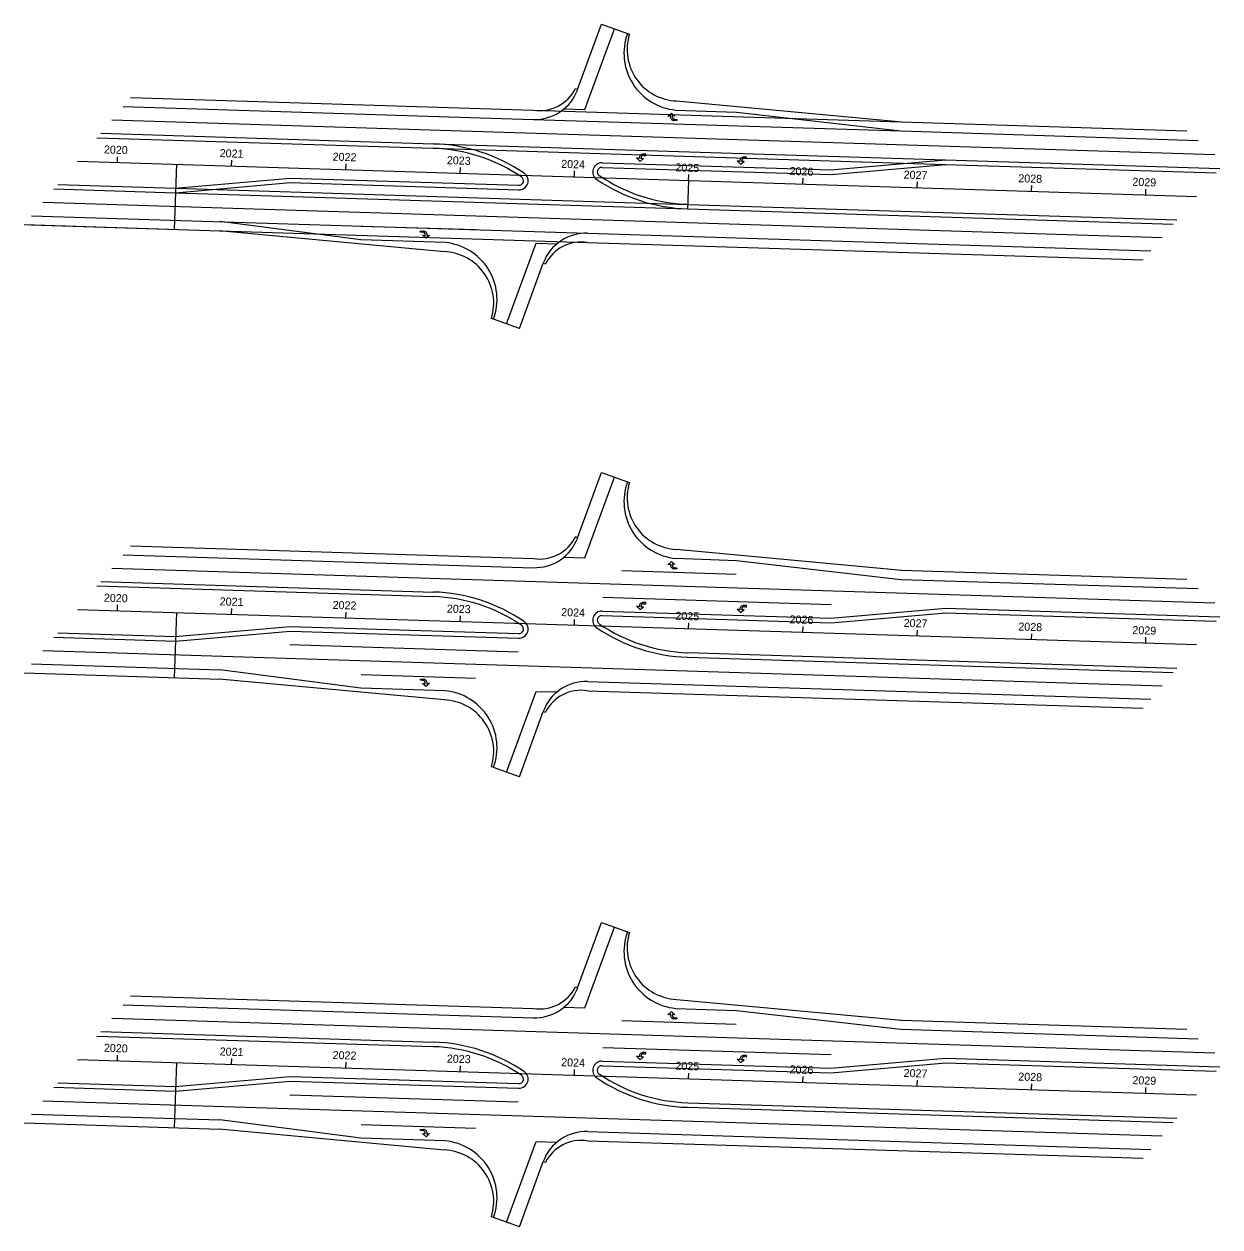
# Model space of a CAD drawing. Extents: x 8527 to 36635, y 12099 to 39012.
# Drawn here: x 11842 to 12888, y 32018 to 33071 of the extents above; entities that cross this region are included whole.
import ezdxf

# ---------------------------------------------------------------- set-up
doc = ezdxf.new("R2010")
doc.units = 0
for name, color, linetype in [('DR_P_Inlet_Protection', 7, 'Continuous'), ('DT_P_Tie', 7, 'Continuous'), ('MT_P_Dotted_Line', 7, 'Continuous'), ('MT_P_Text', 7, 'Continuous'), ('MT_P_Traffic_Attenuator', 7, 'Continuous'), ('PV_X_EOP', 7, 'Continuous'), ('RD_P_Concrete_Barrier', 7, 'Continuous'), ('SH_Text', 7, 'Continuous')]:
    doc.layers.add(name, color=color, linetype=linetype)

msp = doc.modelspace()

# ---------------------------------------------------------------- linework, layer by layer
at = {"layer": 'DR_P_Inlet_Protection'}
for p, q in [((11918.7, 32986.7), (12883.6, 32956.3)), ((11858.2, 32914.6), (12837.3, 32883.7)), ((11918.7, 32594.6), (12883.6, 32564.2)), ((11858.2, 32522.5), (12837.3, 32491.6)), ((11918.7, 32200.9), (12883.6, 32170.5)), ((11858.2, 32128.8), (12837.3, 32097.9))]:
    msp.add_line(p, q, dxfattribs=at)
at = {"layer": 'DT_P_Tie'}
for p, q in [((12314.1, 32996.3), (12332.4, 32995.7)), ((12289.7, 32879), (12308.1, 32878.4)), ((12314.1, 32604.1), (12332.4, 32603.6)), ((12289.7, 32486.8), (12308.1, 32486.3)), ((12314.1, 32210.5), (12332.4, 32209.9)), ((12289.7, 32093.2), (12308.1, 32092.6))]:
    msp.add_line(p, q, dxfattribs=at)
at = {"layer": 'MT_P_Dotted_Line'}
for p, q in [((12332.4, 32995.7), (12358.3, 33066.4)), ((12263.8, 32808.3), (12289.7, 32879)), ((12332.4, 32603.6), (12358.3, 32674.3)), ((12263.8, 32416.1), (12289.7, 32486.8)), ((12332.4, 32209.9), (12358.3, 32280.6)), ((12263.8, 32022.5), (12289.7, 32093.2))]:
    msp.add_line(p, q, dxfattribs=at)
at = {"layer": 'MT_P_Text'}
for p, q in [((11923.5, 32949.6), (11923.6, 32954.5)), ((11888.5, 32950.7), (12867.5, 32919.8)), ((12023.4, 32946.4), (12023.6, 32951.4)), ((12123.4, 32943.3), (12123.6, 32948.3)), ((12223.3, 32940.1), (12223.5, 32945.1)), ((12323.3, 32937), (12323.5, 32942)), ((12423.2, 32933.8), (12423.4, 32938.8)), ((12523.2, 32930.7), (12523.4, 32935.7)), ((12623.1, 32927.5), (12623.3, 32932.5)), ((12723.1, 32924.4), (12723.3, 32929.4)), ((12823, 32921.2), (12823.2, 32926.2)), ((11888.5, 32558.5), (12867.5, 32527.7)), ((11923.5, 32557.4), (11923.6, 32562.4)), ((12023.4, 32554.3), (12023.6, 32559.3)), ((12123.4, 32551.1), (12123.6, 32556.1)), ((12223.3, 32548), (12223.5, 32553)), ((12323.3, 32544.8), (12323.5, 32549.8)), ((12423.2, 32541.7), (12423.4, 32546.7)), ((12523.2, 32538.5), (12523.4, 32543.5)), ((12623.1, 32535.4), (12623.3, 32540.4)), ((12723.1, 32532.2), (12723.3, 32537.2)), ((12823, 32529.1), (12823.2, 32534.1)), ((11923.5, 32163.7), (11923.6, 32168.7)), ((12023.4, 32160.6), (12023.6, 32165.6)), ((11888.5, 32164.8), (12867.5, 32134)), ((12123.4, 32157.4), (12123.6, 32162.4)), ((12223.3, 32154.3), (12223.5, 32159.3)), ((12323.3, 32151.1), (12323.5, 32156.1)), ((12423.2, 32148), (12423.4, 32153)), ((12523.2, 32144.9), (12523.4, 32149.8)), ((12623.1, 32141.7), (12623.3, 32146.7)), ((12723.1, 32138.6), (12723.3, 32143.6)), ((12823, 32135.4), (12823.2, 32140.4))]:
    msp.add_line(p, q, dxfattribs=at)
at = {"layer": 'MT_P_Traffic_Attenuator'}
for p, q in [((12369.6, 33062.3), (12371.5, 33061.6)), ((12326.1, 33013.3), (12324.3, 33014)), ((11935.1, 33006.2), (12287.6, 32995.1)), ((12412.7, 33003.3), (12609.7, 32985)), ((12609.2, 32985), (12858.9, 32977.1)), ((11905.6, 32971.1), (12199.7, 32961.9)), ((12347.5, 32945.2), (12547.4, 32938.9)), ((12547.8, 32938.9), (12648.2, 32947.8)), ((12647.7, 32947.7), (12884.7, 32940.3)), ((11974, 32926.9), (12074.5, 32935.8)), ((12074.5, 32935.8), (12274.7, 32929.5)), ((11871.3, 32930.2), (11974.4, 32926.9)), ((12422.4, 32912.8), (12850.3, 32899.3)), ((11841.8, 32895.1), (12013, 32889.7)), ((12209.5, 32871.4), (12012.5, 32889.7)), ((12334.6, 32879.6), (12820.9, 32864.3)), ((12296, 32861.3), (12297.9, 32860.7)), ((12252.5, 32812.4), (12250.6, 32813.1)), ((12369.6, 32670.1), (12371.5, 32669.4)), ((12326.1, 32621.2), (12324.3, 32621.9)), ((11935.1, 32614.1), (12287.6, 32603)), ((12412.7, 32611.1), (12609.7, 32592.8)), ((12609.2, 32592.8), (12858.9, 32585)), ((11905.6, 32579), (12199.7, 32569.7)), ((12547.8, 32546.8), (12648.2, 32555.6)), ((12647.7, 32555.6), (12884.7, 32548.1)), ((12347.5, 32553.1), (12547.4, 32546.8)), ((11871.3, 32538), (11974.4, 32534.8)), ((11974, 32534.8), (12074.5, 32543.7)), ((12074.5, 32543.7), (12274.7, 32537.3)), ((12422.4, 32520.7), (12850.3, 32507.2)), ((11841.8, 32503), (12013, 32497.6)), ((12209.5, 32479.3), (12012.5, 32497.6)), ((12334.6, 32487.4), (12820.9, 32472.1)), ((12296, 32469.2), (12297.9, 32468.5)), ((12252.5, 32420.3), (12250.6, 32421)), ((12369.6, 32276.5), (12371.5, 32275.8)), ((11935.1, 32220.4), (12287.6, 32209.3)), ((12326.1, 32227.5), (12324.3, 32228.2)), ((12412.7, 32217.4), (12609.7, 32199.1)), ((12609.2, 32199.2), (12858.9, 32191.3)), ((11905.6, 32185.3), (12199.7, 32176.1)), ((12347.5, 32159.4), (12547.4, 32153.1)), ((12547.8, 32153.1), (12648.2, 32162)), ((12647.7, 32161.9), (12884.7, 32154.5)), ((11871.3, 32144.4), (11974.4, 32141.1)), ((11974, 32141.1), (12074.5, 32150)), ((12074.5, 32150), (12274.7, 32143.7)), ((12422.4, 32127), (12850.3, 32113.5)), ((11841.8, 32109.3), (12013, 32103.9)), ((12209.5, 32085.6), (12012.5, 32103.9)), ((12334.6, 32093.8), (12820.9, 32078.4)), ((12296, 32075.5), (12297.9, 32074.9)), ((12252.5, 32026.6), (12250.6, 32027.3))]:
    msp.add_line(p, q, dxfattribs=at)
for centre, radius, start, end in [((12414.5, 33048.3), 45.1, 162.8175, 267.6295), ((12292.8, 33030), 35.2, 261.4285, 333.1119), ((12195.1, 32815.9), 146, 55.8753, 88.1958), ((12347.3, 32941.2), 4, 88.1958, 235.8753), ((12274.8, 32933.5), 4, 268.1958, 55.8753), ((12427, 33058.8), 146, 235.8753, 268.1958), ((12207.6, 32826.4), 45.1, 342.8175, 87.6295), ((12329.3, 32844.7), 35.2, 81.4285, 153.1119), ((12414.5, 32656.1), 45.1, 162.8175, 267.6295), ((12292.8, 32637.8), 35.2, 261.4285, 333.1119), ((12195.1, 32423.8), 146, 55.8753, 88.1958), ((12274.8, 32541.3), 4, 268.1958, 55.8753), ((12347.3, 32549.1), 4, 88.1958, 235.8753), ((12427, 32666.6), 146, 235.8753, 268.1958), ((12329.3, 32452.6), 35.2, 81.4285, 153.1119), ((12207.6, 32434.3), 45.1, 342.8175, 87.6295), ((12414.5, 32262.5), 45.1, 162.8175, 267.6295), ((12292.8, 32244.2), 35.2, 261.4285, 333.1119), ((12195.1, 32030.1), 146, 55.8753, 88.1958), ((12347.3, 32155.4), 4, 88.1958, 235.8753), ((12274.8, 32147.7), 4, 268.1958, 55.8753), ((12427, 32272.9), 146, 235.8753, 268.1958), ((12329.3, 32058.9), 35.2, 81.4285, 153.1119), ((12207.6, 32040.6), 45.1, 342.8175, 87.6295)]:
    msp.add_arc(centre, radius, start, end, dxfattribs=at)
at = {"layer": 'PV_X_EOP'}
for p, q in [((12287.3, 32987.1), (12608.9, 32977)), ((12287.6, 32995.1), (12609.2, 32985)), ((12199.9, 32965.9), (12647.8, 32951.7)), ((12199.7, 32961.9), (12647.7, 32947.7)), ((11974.3, 32922.9), (12422.3, 32908.8)), ((11974.4, 32926.9), (12422.4, 32912.8)), ((12136.8, 32893.8), (12236.8, 32890.7)), ((12364.8, 32592.5), (12464.8, 32589.4)), ((12348, 32569.1), (12547.9, 32562.8)), ((12074.3, 32527.7), (12274.2, 32521.4)), ((12136.8, 32501.7), (12236.8, 32498.5)), ((12364.8, 32198.9), (12464.8, 32195.7)), ((12348, 32175.4), (12547.9, 32169.1)), ((12074.3, 32134), (12274.2, 32127.7)), ((12136.8, 32108), (12236.8, 32104.8))]:
    msp.add_line(p, q, dxfattribs=at)
at = {"layer": 'RD_P_Concrete_Barrier'}
for p, q in [((12405, 32989.7), (12408.2, 32992.6)), ((12407.3, 32990.3), (12405, 32989.7)), ((12405, 32989.7), (12405, 32989.7)), ((12407.2, 32989.7), (12407.3, 32990.3)), ((12408.2, 32992.6), (12411.1, 32989.9)), ((12408.9, 32990.3), (12408.8, 32989.6)), ((12411.1, 32989.9), (12408.9, 32990.3)), ((12412.9, 32986.1), (12410.4, 32986.2)), ((12411.1, 32987.2), (12412.9, 32987.1)), ((12412.9, 32987.1), (12412.9, 32986.1)), ((12413, 32989.5), (12413, 32989.5)), ((12385.9, 32956.6), (12383.4, 32956.7)), ((12384, 32955.7), (12385.8, 32955.6)), ((12385.8, 32955.6), (12385.9, 32956.6)), ((12377.7, 32953.5), (12377.7, 32953.5)), ((12380, 32952.8), (12377.7, 32953.5)), ((12377.7, 32953.5), (12380.7, 32950.4)), ((12380, 32953.5), (12380, 32952.8)), ((12380.7, 32950.4), (12383.8, 32953)), ((12381.6, 32952.7), (12381.6, 32953.4)), ((12383.8, 32953), (12381.6, 32952.7)), ((12385.7, 32953.3), (12385.7, 32953.3)), ((12465.7, 32951), (12465.7, 32951)), ((12468, 32950.2), (12465.7, 32951)), ((12465.7, 32951), (12468.7, 32947.9)), ((12468, 32950.9), (12468, 32950.2)), ((12468.7, 32947.9), (12471.8, 32950.4)), ((12469.6, 32950.2), (12469.6, 32950.9)), ((12471.8, 32950.4), (12469.6, 32950.2)), ((12473.8, 32954), (12471.4, 32954.1)), ((12472, 32953.1), (12473.8, 32953)), ((12473.7, 32950.7), (12473.7, 32950.7)), ((12473.8, 32953), (12473.8, 32954)), ((12188.6, 32886.3), (12188.6, 32886.3)), ((12188.7, 32888.6), (12188.7, 32889.6)), ((12188.7, 32889.6), (12191.2, 32889.5)), ((12190.6, 32888.5), (12188.7, 32888.6)), ((12193.5, 32883.1), (12190.5, 32885.9)), ((12190.5, 32885.9), (12192.7, 32885.5)), ((12192.7, 32885.5), (12192.8, 32886.2)), ((12196.6, 32886), (12193.5, 32883.1)), ((12194.4, 32886.1), (12194.3, 32885.4)), ((12194.3, 32885.4), (12196.6, 32886)), ((12196.6, 32886), (12196.6, 32886)), ((12405, 32597.6), (12408.2, 32600.5)), ((12407.3, 32598.2), (12405, 32597.6)), ((12405, 32597.6), (12405, 32597.6)), ((12407.2, 32597.5), (12407.3, 32598.2)), ((12408.2, 32600.5), (12411.1, 32597.7)), ((12408.9, 32598.1), (12408.8, 32597.4)), ((12411.1, 32597.7), (12408.9, 32598.1)), ((12413, 32597.3), (12413, 32597.3)), ((12412.9, 32594), (12410.4, 32594.1)), ((12411.1, 32595.1), (12412.9, 32595)), ((12412.9, 32595), (12412.9, 32594)), ((12377.7, 32561.4), (12377.7, 32561.4)), ((12380, 32560.7), (12377.7, 32561.4)), ((12377.7, 32561.4), (12380.7, 32558.3)), ((12380, 32561.3), (12380, 32560.7)), ((12380.7, 32558.3), (12383.8, 32560.9)), ((12381.6, 32560.6), (12381.6, 32561.3)), ((12383.8, 32560.9), (12381.6, 32560.6)), ((12385.9, 32564.5), (12383.4, 32564.5)), ((12384, 32563.5), (12385.8, 32563.5)), ((12385.7, 32561.1), (12385.7, 32561.1)), ((12385.8, 32563.5), (12385.9, 32564.5)), ((12465.7, 32558.8), (12465.7, 32558.8)), ((12468, 32558.1), (12465.7, 32558.8)), ((12465.7, 32558.8), (12468.7, 32555.7)), ((12468, 32558.7), (12468, 32558.1)), ((12468.7, 32555.7), (12471.8, 32558.3)), ((12469.6, 32558), (12469.6, 32558.7)), ((12471.8, 32558.3), (12469.6, 32558)), ((12473.8, 32561.9), (12471.4, 32562)), ((12472, 32560.9), (12473.8, 32560.9)), ((12473.7, 32558.5), (12473.7, 32558.5)), ((12473.8, 32560.9), (12473.8, 32561.9)), ((12188.6, 32494.1), (12188.6, 32494.1)), ((12188.7, 32496.5), (12188.7, 32497.5)), ((12188.7, 32497.5), (12191.2, 32497.4)), ((12190.6, 32496.4), (12188.7, 32496.5)), ((12193.5, 32491), (12190.5, 32493.7)), ((12190.5, 32493.7), (12192.7, 32493.3)), ((12192.7, 32493.3), (12192.8, 32494)), ((12196.6, 32493.9), (12193.5, 32491)), ((12194.4, 32493.9), (12194.3, 32493.3)), ((12194.3, 32493.3), (12196.6, 32493.9)), ((12196.6, 32493.9), (12196.6, 32493.9)), ((12405, 32203.9), (12408.2, 32206.8)), ((12407.3, 32204.5), (12405, 32203.9)), ((12405, 32203.9), (12405, 32203.9)), ((12407.2, 32203.9), (12407.3, 32204.5)), ((12408.2, 32206.8), (12411.1, 32204)), ((12408.9, 32204.5), (12408.8, 32203.8)), ((12411.1, 32204), (12408.9, 32204.5)), ((12412.9, 32200.3), (12410.4, 32200.4)), ((12411.1, 32201.4), (12412.9, 32201.3)), ((12412.9, 32201.3), (12412.9, 32200.3)), ((12413, 32203.6), (12413, 32203.6)), ((12377.7, 32167.7), (12377.7, 32167.7)), ((12380, 32167), (12377.7, 32167.7)), ((12377.7, 32167.7), (12380.7, 32164.6)), ((12380, 32167.7), (12380, 32167)), ((12380.7, 32164.6), (12383.8, 32167.2)), ((12381.6, 32166.9), (12381.6, 32167.6)), ((12383.8, 32167.2), (12381.6, 32166.9)), ((12385.9, 32170.8), (12383.4, 32170.9)), ((12384, 32169.9), (12385.8, 32169.8)), ((12385.7, 32167.5), (12385.7, 32167.5)), ((12385.8, 32169.8), (12385.9, 32170.8)), ((12473.8, 32168.2), (12471.4, 32168.3)), ((12472, 32167.3), (12473.8, 32167.2)), ((12473.8, 32167.2), (12473.8, 32168.2)), ((12465.7, 32165.2), (12465.7, 32165.2)), ((12468, 32164.4), (12465.7, 32165.2)), ((12465.7, 32165.2), (12468.7, 32162.1)), ((12468, 32165.1), (12468, 32164.4)), ((12468.7, 32162.1), (12471.8, 32164.6)), ((12469.6, 32164.4), (12469.6, 32165.1)), ((12471.8, 32164.6), (12469.6, 32164.4)), ((12473.7, 32164.9), (12473.7, 32164.9)), ((12188.7, 32102.8), (12188.7, 32103.8)), ((12188.7, 32103.8), (12191.2, 32103.7)), ((12190.6, 32102.7), (12188.7, 32102.8)), ((12188.6, 32100.5), (12188.6, 32100.5)), ((12193.5, 32097.3), (12190.5, 32100.1)), ((12190.5, 32100.1), (12192.7, 32099.7)), ((12192.7, 32099.7), (12192.8, 32100.4)), ((12196.6, 32100.2), (12193.5, 32097.3)), ((12194.4, 32100.3), (12194.3, 32099.6)), ((12194.3, 32099.6), (12196.6, 32100.2)), ((12196.6, 32100.2), (12196.6, 32100.2))]:
    msp.add_line(p, q, dxfattribs=at)
for centre, radius, start, end in [((12410.5, 32989.5), 3.28, 177.0915, 268), ((12411.1, 32989.5), 2.3, 178, 268), ((12383.3, 32953.4), 3.28, 88, 178.9085), ((12383.9, 32953.4), 2.3, 88, 178), ((12471.3, 32950.8), 3.28, 88, 178.9085), ((12471.9, 32950.8), 2.3, 88, 178), ((12190.5, 32886.2), 2.3, 358, 88), ((12191.1, 32886.2), 3.28, 357.0915, 88), ((12410.5, 32597.4), 3.28, 177.0915, 268), ((12411.1, 32597.3), 2.3, 178, 268), ((12383.3, 32561.3), 3.28, 88, 178.9085), ((12383.9, 32561.2), 2.3, 88, 178), ((12471.3, 32558.7), 3.28, 88, 178.9085), ((12471.9, 32558.7), 2.3, 88, 178), ((12190.5, 32494.1), 2.3, 358, 88), ((12191.1, 32494.1), 3.28, 357.0915, 88), ((12410.5, 32203.7), 3.28, 177.0915, 268), ((12411.1, 32203.7), 2.3, 178, 268), ((12383.3, 32167.6), 3.28, 88, 178.9085), ((12383.9, 32167.6), 2.3, 88, 178), ((12471.3, 32165), 3.28, 88, 178.9085), ((12471.9, 32165), 2.3, 88, 178), ((12190.5, 32100.4), 2.3, 358, 88), ((12191.1, 32100.4), 3.28, 357.0915, 88)]:
    msp.add_arc(centre, radius, start, end, dxfattribs=at)
at = {"layer": 'SH_Text'}
for p, q in [((12326.1, 33013.3), (12347.1, 33070.5)), ((12347.1, 33070.5), (12369.6, 33062.3)), ((11928.5, 32998.4), (12287.3, 32987.1)), ((12608.9, 32977), (12868.8, 32968.8)), ((11908.9, 32975), (12199.9, 32965.9)), ((11975.1, 32947.9), (11973.3, 32891)), ((12347.6, 32949.2), (12547.5, 32942.9)), ((12547.5, 32942.9), (12647.8, 32951.7)), ((12647.8, 32951.7), (12888, 32944.2)), ((12423.1, 32933.8), (12422.3, 32908.8)), ((11868, 32926.3), (11974.3, 32922.9)), ((11974.3, 32922.9), (12074.6, 32931.8)), ((12074.6, 32931.8), (12274.5, 32925.5)), ((11848.4, 32902.9), (12334.8, 32887.6)), ((12422.3, 32908.8), (12847.1, 32895.4)), ((11848.1, 32894.9), (12334.6, 32879.6)), ((12334.8, 32887.6), (12827.4, 32872.1)), ((12275.1, 32804.2), (12296, 32861.3)), ((12275.1, 32804.2), (12252.5, 32812.4)), ((12326.1, 32621.2), (12347.1, 32678.4)), ((12347.1, 32678.4), (12369.6, 32670.1)), ((11928.5, 32606.3), (12287.3, 32595)), ((11908.9, 32582.9), (12199.9, 32573.7)), ((12608.9, 32584.8), (12868.8, 32576.7)), ((11975.1, 32555.8), (11973.3, 32498.8)), ((12347.6, 32557.1), (12547.5, 32550.8)), ((12547.5, 32550.8), (12647.8, 32559.6)), ((12647.8, 32559.6), (12888, 32552)), ((11868, 32534.1), (11974.3, 32530.8)), ((11974.3, 32530.8), (12074.6, 32539.6)), ((12074.6, 32539.6), (12274.5, 32533.3)), ((12422.3, 32516.7), (12847.1, 32503.3)), ((11848.4, 32510.8), (12013.2, 32505.6)), ((12334.8, 32495.4), (12827.4, 32479.9)), ((12275.1, 32412), (12296, 32469.2)), ((12275.1, 32412), (12252.5, 32420.3)), ((12326.1, 32227.5), (12347.1, 32284.7)), ((12347.1, 32284.7), (12369.6, 32276.5)), ((11928.5, 32212.6), (12287.3, 32201.3)), ((11908.9, 32189.2), (12199.9, 32180)), ((12608.9, 32191.2), (12868.8, 32183)), ((12547.5, 32157.1), (12647.8, 32165.9)), ((12647.8, 32165.9), (12888, 32158.4)), ((11975.1, 32162.1), (11973.3, 32105.1)), ((12347.6, 32163.4), (12547.5, 32157.1)), ((11974.3, 32137.1), (12074.6, 32146)), ((12074.6, 32146), (12274.5, 32139.7)), ((11868, 32140.5), (11974.3, 32137.1)), ((11848.4, 32117.1), (12013.2, 32111.9)), ((12422.3, 32123), (12847.1, 32109.6)), ((12334.8, 32101.8), (12827.4, 32086.2)), ((12275.1, 32018.3), (12296, 32075.5)), ((12275.1, 32018.3), (12252.5, 32026.6))]:
    msp.add_line(p, q, dxfattribs=at)
for points in [[(12411.9, 32995.3), (12465.1, 32993.5), (12608.9, 32977)], [(12210.2, 32879.4), (12136.5, 32881.8), (12013.2, 32897.7)], [(12411.9, 32603.2), (12465.1, 32601.4), (12608.9, 32584.8)], [(12210.2, 32487.3), (12136.5, 32489.7), (12013.2, 32505.6)], [(12411.9, 32209.5), (12465.1, 32207.7), (12608.9, 32191.2)], [(12210.2, 32093.6), (12136.5, 32096), (12013.2, 32111.9)]]:
    msp.add_lwpolyline(points, dxfattribs=at)
for centre, radius, start, end in [((12416.6, 33045.1), 50, 159.8792, 264.6911), ((12288.6, 33027.1), 40, 268.1958, 339.8792), ((12195.1, 32815.9), 150, 55.8753, 88.1958), ((12347.3, 32941.2), 8, 88.1958, 235.8753), ((12274.8, 32933.5), 8, 268.1958, 55.8753), ((12427, 33058.8), 150, 235.8753, 268.1958), ((12333.6, 32847.6), 40, 88.1958, 159.8792), ((12205.6, 32829.6), 50, 339.8792, 84.6911), ((12416.6, 32652.9), 50, 159.8792, 264.6911), ((12288.6, 32635), 40, 268.1958, 339.8792), ((12195.1, 32423.8), 150, 55.8753, 88.1958), ((12347.3, 32549.1), 8, 88.1958, 235.8753), ((12274.8, 32541.3), 8, 268.1958, 55.8753), ((12427, 32666.6), 150, 235.8753, 268.1958), ((12333.6, 32455.5), 40, 88.1958, 159.8792), ((12205.6, 32437.5), 50, 339.8792, 84.6911), ((12416.6, 32259.3), 50, 159.8792, 264.6911), ((12288.6, 32241.3), 40, 268.1958, 339.8792), ((12195.1, 32030.1), 150, 55.8753, 88.1958), ((12347.3, 32155.4), 8, 88.1958, 235.8753), ((12274.8, 32147.7), 8, 268.1958, 55.8753), ((12427, 32272.9), 150, 235.8753, 268.1958), ((12205.6, 32043.8), 50, 339.8792, 84.6911), ((12333.6, 32061.8), 40, 88.1958, 159.8792)]:
    msp.add_arc(centre, radius, start, end, dxfattribs=at)

# ---------------------------------------------------------------- texts
at = {"layer": 'MT_P_Text'}
for s, p in [('2020', (11911.6, 32957.4)), ('2021', (12012.9, 32954.2)), ('2022', (12111.7, 32951.1)), ('2023', (12211.6, 32948)), ('2024', (12311.6, 32944.8)), ('2025', (12411.5, 32941.7)), ('2026', (12511.4, 32938.5)), ('2027', (12611.2, 32935.4)), ('2028', (12711.5, 32932.2)), ('2029', (12811.3, 32929.1)), ('2020', (11911.6, 32565.3)), ('2021', (12012.9, 32562.1)), ('2022', (12111.7, 32559)), ('2023', (12211.6, 32555.8)), ('2024', (12311.6, 32552.7)), ('2025', (12411.5, 32549.5)), ('2026', (12511.4, 32546.4)), ('2027', (12611.2, 32543.3)), ('2028', (12711.5, 32540.1)), ('2029', (12811.3, 32537)), ('2020', (11911.6, 32171.6)), ('2021', (12012.9, 32168.4)), ('2022', (12111.7, 32165.3)), ('2023', (12211.6, 32162.2)), ('2024', (12311.6, 32159)), ('2025', (12411.5, 32155.9)), ('2026', (12511.4, 32152.7)), ('2027', (12611.2, 32149.6)), ('2028', (12711.5, 32146.4)), ('2029', (12811.3, 32143.3))]:
    msp.add_text(s, height=7, rotation=358.1958, dxfattribs=at).set_placement(p)

doc.saveas('drawing.dxf')
